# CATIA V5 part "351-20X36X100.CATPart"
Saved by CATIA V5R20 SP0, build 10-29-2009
Part number: 351-20X36X100
Definition: NONE
Nomenclature: 351-20X36X100
Source: Unknown
Description: 351-20X36X100
Bounding box of the stored display mesh (mm): x -6 to 94, y -16 to 16, z -16 to 16
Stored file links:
  C:\Users\Utente\Desktop\IO LAVORO\3D X SITO CF\X SITO\PLASTICA\351\351-20X36X100.CATPart
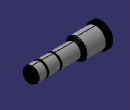
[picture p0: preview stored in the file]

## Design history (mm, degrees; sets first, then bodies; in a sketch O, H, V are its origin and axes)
Body1 "351-20X36X100" (main body)
  Solid1: solid without history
